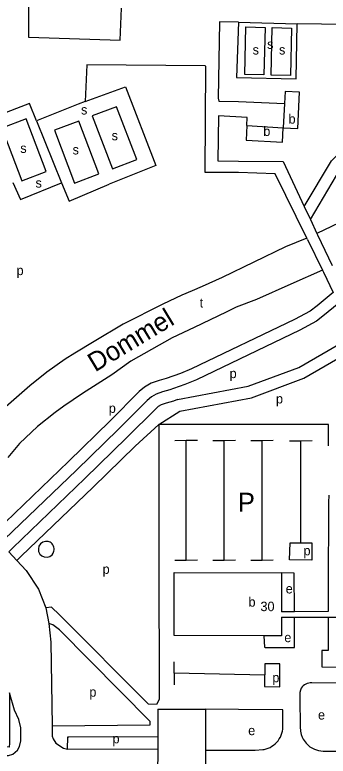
# Model space of a CAD drawing. Extents: x 161494 to 163033, y 383688 to 384862.
# Drawn here: x 161805.5 to 161937.8, y 384379.7 to 384692.8 of the extents above; entities that cross this region are included whole.
import ezdxf

# ---------------------------------------------------------------- set-up
doc = ezdxf.new("R2010")
doc.units = 0
for name, color, linetype in [('BLT_Basislijn', 7, 'Continuous'), ('BLT_Bebouwing', 7, 'Continuous'), ('BLT_Centroide', 7, 'Continuous'), ('BLT_Huisnummer', 7, 'Continuous'), ('BLT_Tekst_parkeren', 7, 'Continuous'), ('BLT_Waternaam_spoorwegen', 7, 'Continuous')]:
    doc.layers.add(name, color=color, linetype=linetype)

msp = doc.modelspace()

# ---------------------------------------------------------------- linework, layer by layer
at = {"layer": 'BLT_Basislijn'}
for p, q in [((161900, 384689.72), (161924.77, 384689)), ((162011.86, 384687.67), (161924.77, 384689)), ((161811.74, 384655.29), (161793.85, 384648.38)), ((161814.64, 384648.04), (161811.74, 384655.29)), ((161832.2, 384654.99), (161814.64, 384648.04)), ((161814.64, 384648.04), (161825.19, 384621.75)), ((161933.1, 384600.35), (161933.32, 384599.9)), ((161933.32, 384599.9), (161939.51, 384586.93)), ((161929.11, 384597.88), (161928.83, 384598.45)), ((161929.11, 384597.88), (161935.43, 384584.87)), ((161935.43, 384584.87), (161935.8, 384584.12)), ((161935.8, 384584.12), (161939.88, 384575.55)), ((161873.09, 384513.03), (161877.84, 384513.11)), ((161877.84, 384513.11), (161882.58, 384513.18)), ((161877.84, 384462.53), (161877.84, 384513.11)), ((161889.14, 384513), (161893.89, 384513.07)), ((161893.89, 384513.07), (161898.63, 384513.15)), ((161893.89, 384462.5), (161893.89, 384513.07)), ((161905.16, 384512.98), (161909.9, 384513.06)), ((161909.9, 384513.06), (161914.65, 384513.14)), ((161909.9, 384462.49), (161909.9, 384513.06)), ((161921.53, 384512.83), (161926.28, 384512.91)), ((161926.28, 384512.91), (161931.02, 384512.98)), ((161926.28, 384469.8), (161926.28, 384512.91)), ((161802.96, 384465.98), (161806.43, 384462.37)), ((161873.09, 384462.45), (161877.84, 384462.53)), ((161877.84, 384462.53), (161882.58, 384462.61)), ((161889.14, 384462.42), (161893.89, 384462.5)), ((161893.89, 384462.5), (161898.63, 384462.58)), ((161905.16, 384462.41), (161909.9, 384462.49)), ((161909.9, 384462.49), (161914.65, 384462.56)), ((161818.66, 384442.29), (161819.94, 384435.73)), ((161872.81, 384414.69), (161872.82, 384419.6)), ((161911.01, 384413.92), (161872.81, 384414.69)), ((161872.81, 384414.69), (161872.81, 384409.78))]:
    msp.add_line(p, q, dxfattribs=at)
for points in [[(161811.31, 384698.49), (161811.31, 384683.25), (161820.02, 384683.07)], [(161820.02, 384683.07), (161850.02, 384682.12), (161850.61, 384695.61)], [(161900, 384689.72), (161892.1, 384689.8), (161891.87, 384689.61), (161891.35, 384657.6), (161891.7, 384656.23), (161900, 384656.15), (161919.34, 384655.25)], [(161900, 384689.72), (161899.08, 384666.24), (161924.26, 384665.69), (161924.77, 384689)], [(161927.72, 384611.79), (161939.21, 384631.09), (161972.91, 384664.14), (161995.43, 384676.54), (162011.86, 384687.48)], [(161930.29, 384606.33), (161943.18, 384627.98), (161975.92, 384660.1), (161998.03, 384672.26), (162012.19, 384681.69)], [(161928.83, 384598.45), (161915.45, 384625.64), (161900, 384626.13), (161885.86, 384626.23), (161886.12, 384670.99), (161885.86, 384671.26), (161835.85, 384671.62), (161835.2, 384656.2)], [(161835.2, 384656.2), (161852.27, 384662.33), (161865.02, 384629.12), (161845.38, 384621.23)], [(161835.2, 384656.2), (161832.2, 384654.99)], [(161856.97, 384631.65), (161848.47, 384653.95), (161838.22, 384650.05), (161846.72, 384627.74), (161856.97, 384631.65)], [(161903.48, 384645.95), (161903.68, 384649.43), (161891.49, 384650.11), (161891.25, 384631.07), (161900, 384630.95), (161918.79, 384630.77), (161927.72, 384611.79)], [(161818.77, 384626.55), (161810.27, 384648.86), (161800.03, 384644.95), (161808.52, 384622.65), (161818.77, 384626.55)], [(161841.01, 384625.6), (161832.52, 384647.9), (161822.27, 384643.99), (161830.76, 384621.69), (161841.01, 384625.6)], [(161804.61, 384621.95), (161807.86, 384614.76), (161825.19, 384621.75)], [(161825.19, 384621.75), (161828.4, 384614.05), (161845.38, 384621.23)], [(161965.3, 384615.12), (161951.55, 384609.34), (161933.1, 384600.35)], [(161927.72, 384611.79), (161930.29, 384606.33)], [(161930.29, 384606.33), (161933.1, 384600.35)], [(161928.83, 384598.45), (161919.83, 384594.84), (161906.47, 384588.3), (161893.11, 384581.77), (161884.59, 384578.08), (161880.34, 384576.26)], [(161935.43, 384584.87), (161922.03, 384578.98), (161907.52, 384572.61), (161898.94, 384569.32), (161894.77, 384567.17), (161881.29, 384560.67)], [(161939.88, 384575.55), (161933.16, 384569.9), (161930.17, 384567.61), (161923.57, 384564.05), (161880.13, 384543.25), (161875.48, 384541.33), (161869.42, 384539.18), (161866.4, 384538.3), (161863.11, 384537.18), (161860.29, 384535.54), (161858.06, 384533.63), (161845.78, 384521.31), (161828.11, 384504.08), (161797.59, 384474.82), (161795.64, 384472.79)], [(161880.34, 384576.26), (161876.08, 384574.39), (161867.97, 384570.54), (161851.3, 384562.09), (161839, 384554.76)], [(161941.64, 384570.5), (161936.29, 384566.01), (161932.9, 384563.4), (161925.84, 384559.59), (161882.17, 384538.68)], [(161881.29, 384560.67), (161871.99, 384556.32), (161854.55, 384546.54), (161846.45, 384540.79)], [(161874.22, 384530.27), (161904.04, 384535.88), (161925.46, 384543.89), (161951.91, 384559.21)], [(161839, 384554.76), (161830.84, 384549.88), (161826.82, 384547.41), (161819.08, 384541.83), (161811.82, 384536.14), (161803.97, 384529.16), (161796.27, 384522.62)], [(161866.38, 384519.73), (161875.14, 384525.35), (161905.39, 384531.04), (161927.61, 384539.35), (161954.55, 384554.96)], [(161846.45, 384540.79), (161834.11, 384532.91), (161826.23, 384527.48), (161822.52, 384524.85), (161815.04, 384518.96), (161807.43, 384511.78), (161802.53, 384505.89)], [(161882.17, 384538.68), (161877.28, 384536.66), (161872.55, 384534.98)], [(161872.55, 384534.98), (161870.96, 384534.42), (161867.9, 384533.53), (161865.19, 384532.6), (161863.19, 384531.45), (161861.46, 384529.96), (161849.3, 384517.75), (161831.58, 384500.48), (161801.12, 384471.28), (161799.32, 384469.4)], [(161874.22, 384530.27), (161872.5, 384529.66), (161869.41, 384528.76), (161867.27, 384528.03), (161866.1, 384527.35), (161864.87, 384526.3), (161852.81, 384514.2), (161835.06, 384496.89), (161804.66, 384467.74), (161802.96, 384465.98)], [(161866.38, 384519.73), (161856.33, 384510.64), (161838.53, 384493.29), (161808.19, 384464.21), (161806.43, 384462.37)], [(161866.38, 384519.73), (161866.35, 384463.43)], [(161937.92, 384510.81), (161937.97, 384519.69), (161866.38, 384519.73)], [(161938.06, 384489.92), (161937.9, 384486.8), (161937.83, 384449.68), (161937.82, 384440.72)], [(161819.54, 384470.34), (161818.42, 384470.4), (161817.28, 384470.06), (161816.32, 384469.34), (161815.71, 384468.38), (161815.45, 384467.31), (161815.57, 384466.13), (161816.11, 384465.06), (161816.95, 384464.27), (161817.95, 384463.82), (161819.12, 384463.73), (161820.28, 384464.07), (161821.22, 384464.76), (161821.68, 384465.37), (161821.89, 384465.8), (161822.05, 384466.27), (161822.13, 384466.79), (161822.13, 384467.34), (161822.04, 384467.89), (161821.86, 384468.43), (161821.59, 384468.92), (161821.24, 384469.36), (161820.85, 384469.72), (161820.42, 384470), (161819.97, 384470.21), (161819.54, 384470.34)], [(161926.28, 384469.8), (161930.9, 384469.8), (161930.95, 384462.45), (161921.54, 384462.57), (161921.74, 384469.8), (161926.28, 384469.8)], [(161806.43, 384462.37), (161810.24, 384458.13), (161815.58, 384450.27), (161818.66, 384442.29)], [(161866.35, 384463.43), (161866.39, 384403.61), (161865.38, 384401.47)], [(161923.56, 384440.71), (161923.5, 384457.03), (161918.05, 384457.11)], [(161865.38, 384401.47), (161861.9, 384401.6), (161824.39, 384439.38), (161820.99, 384442.58), (161818.66, 384442.29)], [(161910.71, 384430.56), (161910.96, 384425.75), (161911.2, 384425.55), (161923.57, 384425.55), (161923.57, 384438.33)], [(161937.81, 384438.33), (161937.79, 384424.39), (161935.09, 384424.39), (161935.11, 384421.74)], [(161819.94, 384435.73), (161820.7, 384427.8), (161821.25, 384392.45)], [(161821.25, 384392.45), (161862.62, 384392.95), (161862.65, 384394.3), (161824.39, 384433.08), (161821.62, 384435.22), (161819.94, 384435.73)], [(161935.11, 384421.74), (161935.13, 384417.47), (161947.42, 384417.17)], [(161917.38, 384413.88), (161917.38, 384418.74), (161911.07, 384418.72), (161910.96, 384409.12), (161917.37, 384408.99), (161917.38, 384413.88)], [(161947.42, 384410.59), (161930.9, 384410.67), (161930.25, 384410.65), (161929.61, 384410.55), (161928.98, 384410.38), (161928.39, 384410.13), (161927.82, 384409.8), (161927.31, 384409.42), (161926.84, 384408.96), (161926.43, 384408.46), (161926.09, 384407.54), (161925.87, 384406.59), (161925.89, 384404.18), (161925.93, 384392.05), (161926.1, 384390.22), (161926.44, 384388.78), (161926.86, 384387.75), (161927.3, 384386.88), (161928.5, 384385.23), (161930.12, 384383.71), (161932, 384382.63), (161933.72, 384382.03), (161935.75, 384381.78), (161950, 384381.82)], [(161803.2, 384406.39), (161803.2, 384385.17), (161803.08, 384383.57), (161798.15, 384383.59), (161798.3, 384380.78), (161800.29, 384379.98), (161802.89, 384379.98), (161804.68, 384380.58), (161806.68, 384382.18), (161807.47, 384383.77), (161808.07, 384386.17), (161808.08, 384389.36), (161808.06, 384391.6), (161807.25, 384395.24), (161805.4, 384399.17), (161803.2, 384406.39)], [(161910.19, 384382.47), (161910.78, 384382.56), (161911.64, 384382.78), (161912.48, 384383.06), (161913.29, 384383.43), (161914.06, 384383.86), (161914.8, 384384.36), (161915.48, 384384.93), (161916.11, 384385.55), (161916.68, 384386.23), (161917.18, 384386.96), (161917.62, 384387.73), (161917.99, 384388.54), (161918.28, 384389.37), (161918.5, 384390.23), (161918.64, 384391.11), (161918.66, 384399.31), (161900, 384399.42), (161886.16, 384399.52)], [(161821.25, 384392.45), (161821.34, 384388.21), (161821.73, 384386.98), (161822.81, 384385.23), (161826.04, 384383.01), (161827.75, 384382.66)], [(161827.75, 384382.66), (161827.9, 384387.83), (161828.27, 384387.91), (161865.88, 384387.98)], [(161865.85, 384382.45), (161827.75, 384382.66)], [(161886.18, 384382.29), (161900, 384382.24), (161907, 384382.22), (161910.19, 384382.47)]]:
    msp.add_lwpolyline(points, dxfattribs=at)
for points in [[(161903.1, 384687.67), (161911.17, 384687.44), (161910.72, 384667.39), (161902.67, 384667.57)], [(161914.24, 384687.38), (161922.31, 384687.15), (161921.85, 384667.1), (161913.8, 384667.29)]]:
    msp.add_lwpolyline(points, close=True, dxfattribs=at)
at = {"layer": 'BLT_Bebouwing'}
for p, q in [((161903.48, 384645.95), (161918.81, 384645.07)), ((161865.94, 384399.61), (161865.88, 384387.98)), ((161865.94, 384399.61), (161886.16, 384399.52)), ((161886.18, 384382.29), (161886.16, 384399.52)), ((161865.88, 384387.98), (161865.85, 384382.45)), ((161865.85, 384382.45), (161865.76, 384366.98)), ((161886.19, 384365.72), (161886.18, 384382.29))]:
    msp.add_line(p, q, dxfattribs=at)
for points in [[(161924.94, 384644.74), (161925.75, 384660.07), (161919.61, 384660.4), (161919.34, 384655.25)], [(161919.34, 384655.25), (161918.81, 384645.07)], [(161903.48, 384645.95), (161903.16, 384639.81), (161918.49, 384639.02), (161918.81, 384645.07)], [(161918.81, 384645.07), (161924.94, 384644.74)], [(161910.71, 384430.56), (161872.81, 384430.61), (161872.84, 384457.22), (161918.05, 384457.11)], [(161918.05, 384457.11), (161918.05, 384440.71)], [(161923.56, 384440.71), (161918.05, 384440.71)], [(161937.82, 384440.72), (161923.56, 384440.71)], [(161918.05, 384438.33), (161918.05, 384430.55), (161910.71, 384430.56)], [(161918.05, 384438.33), (161923.57, 384438.33)], [(161923.57, 384438.33), (161937.81, 384438.33)], [(161937.81, 384438.33), (161947.41, 384438.33)]]:
    msp.add_lwpolyline(points, dxfattribs=at)

# ---------------------------------------------------------------- texts
at = {"layer": 'BLT_Centroide'}
for s, p in [('s', (161912.03, 384678.38)), ('s', (161905.92, 384676)), ('s', (161917.06, 384676)), ('s', (161833.46, 384650.67)), ('b', (161921.08, 384646.81)), ('b', (161910.42, 384641.6)), ('s', (161846.4, 384639.77)), ('s', (161807.83, 384634.45)), ('s', (161829.9, 384633.8)), ('s', (161814.25, 384619.78)), ('p', (161806.24, 384582.85)), ('t', (161883.56, 384569.17)), ('p', (161896.2, 384539.34)), ('p', (161915.77, 384528.64)), ('p', (161845.19, 384524.66)), ('p', (161927.41, 384464.51)), ('p', (161842.57, 384456.7)), ('e', (161919.89, 384448.42)), ('b', (161904.18, 384442.83)), ('e', (161919.31, 384427.85)), ('p', (161914.25, 384410.91)), ('p', (161836.98, 384404.81)), ('e', (161933.52, 384395.15)), ('e', (161904.04, 384388.57)), ('p', (161846.76, 384385.12))]:
    msp.add_text(s, height=4, dxfattribs=at).set_placement(p)
at = {"layer": 'BLT_Huisnummer'}
msp.add_text('30', height=4, rotation=359.77, dxfattribs=at).set_placement((161909.21, 384440.95))
at = {"layer": 'BLT_Tekst_parkeren'}
msp.add_text('P', height=8, dxfattribs=at).set_placement((161899.74, 384482.94))
at = {"layer": 'BLT_Waternaam_spoorwegen'}
msp.add_text('Dommel', height=8, rotation=31.1859, dxfattribs=at).set_placement((161839.41, 384541.73))

doc.saveas('drawing.dxf')
